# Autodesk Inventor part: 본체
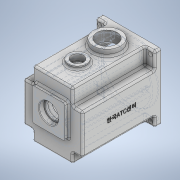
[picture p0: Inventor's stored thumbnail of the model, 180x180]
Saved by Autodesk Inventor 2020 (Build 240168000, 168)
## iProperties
Created: 2022-01
Part Number: 본체
Material: 일반
Document SubType Name: Modeling
Designer: user
Density: 1 g/cm^3
Appearance: 기본값
Mass: 519.685 g
Surface Area: 1174.34 cm^2
Volume: 519.685 cm^3
Author: user
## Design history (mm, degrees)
sketch "스케치1"
  geometry: 1 further point
sketch "스케치2"
  geometry: L1 (-49, 55)-(49, 55); L2 (49, 55)-(49, -55); L3 (49, -55)-(-49, -55); L4 (-49, -55)-(-49, 55); L5 (-49, 55)-(49, -55); L6 (49, 55)-(-49, -55); 1 further point
  constraints: 12 end point, 2 midpoint, 2 parallel, 1 horizontal, 1 perpendicular
  dimensions: "d0" = 98 distance of L2.end L3.end; "d1" = 110 distance of L1.end L2.end
extrude "돌출1" new body sketch "스케치2" distance "d2" = 10; taper "d3" = 0 deg
sketch "스케치3"
  geometry: L1 (49, -55)-(49, 55) reference; L2 (49, 55)-(-49, 55) reference; L3 (-49, 55)-(-49, -55) reference; L4 (-49, -55)-(49, -55) reference; L5 (49, -55)-(49, 55) reference; L6 (49, 55)-(33, 55); L7 (33, 55)-(33, 28); L8 (33, 28)-(49, 28); L9 (49, 28)-(49, 55); L10 (49, -55)-(33, -55); L11 (33, -55)-(33, -38); L12 (33, -38)-(49, -38); L13 (49, -38)-(49, -55); L14 (-49, -55)-(49, -55) reference; L15 (-49, -55)-(-33, -55); L16 (-33, -55)-(-33, -38); L17 (-33, -38)-(-49, -38); L18 (-49, -38)-(-49, -55); L19 (-49, 55)-(-49, -55) reference; L20 (-49, 55)-(-33, 55); L21 (-33, 55)-(-33, 28); L22 (-33, 28)-(-49, 28); L23 (-49, 28)-(-49, 55); 9 further points
  constraints: 32 end point, 8 parallel, 4 horizontal, 4 perpendicular, 1 point on line
  dimensions: "d4" = 27 distance of L6.end L7.end; "d5" = 16 distance of L7.end L8.end; "d6" = 17 distance of L10.end L11.end; "d7" = 16 distance of L11.end L12.end; "d8" = 27 distance of L20.end L21.end; "d9" = 16 distance of L21.end L22.end; "d10" = 16 distance of L16.end L17.end
extrude "돌출2" join sketch "스케치3" distance "d11" = 120; taper "d12" = 0 deg
sketch "스케치4"
  geometry: 1 further point
sketch "스케치5"
  geometry: L1 (49, -55)-(-49, -55) reference; L2 (-26, 48)-(26, 48); L3 (26, 48)-(26, 27.588); L4 (26, 27.588)-(-26, 27.588); L5 (-26, 27.588)-(-26, 48); C1 r 45 at (0, -5); 3 further points
  constraints: 8 end point, 2 parallel, 1 centre point, 1 horizontal, 1 perpendicular, 1 vertical alignment
  dimensions: "d13" = 90 diameter of C1; "d14" = 50 distance from line of L1 C1.centre; "d15" = 53 distance from line of L2 C1.centre; "d16" = 52 distance of L2.start L2.end; "d17" = 26 horizontal distance of C1.centre L2.start
extrude "돌출3" cut sketch "스케치5" distance "d18" = 9; taper "d19" = 0 deg
sketch "스케치6" dims "d27" = 8, "d28" = 8
  geometry: L1 (-26, 31.729)-(-26, 48) reference; L2 (26, 48)-(26, 31.729) reference; L3 (-26, 48)-(26, 48) reference; L4 (-23, 45)-(23, 45); L5 (23, 45)-(23, 21.058); L6 (23, 21.058)-(-23, 21.058); L7 (-23, 21.058)-(-23, 45); L8 (-35.778, -1.006)-(-41.81, -1.006); L9 (-35.778, -8.994)-(-41.81, -8.994); L10 (35.778, -1.006)-(42, -1.006); L11 (35.778, -8.994)-(41.81, -8.994); A1 r 45 centre (0, -5) between (-26, 31.729) and (26, 31.729) reference; A2 r 36 centre (0, -5) between (36, -5) and (-36, -5); A3 r 42 centre (0, -5) between (-41.81, -8.994) and (41.81, -8.994); A4 r 42 centre (0, -5) between (41.81, -1.006) and (-41.81, -1.006); 7 further points
  constraints: 16 end point, 10 point on circle, 4 horizontal, 3 centre point, 2 coincident, 2 horizontal alignment, 2 parallel, 1 perpendicular, 1 point on line, 6 other
  dimensions: "d21" = 46 distance of L4.start L4.end; "d22" = 23 distance from line of A1.centre L7; "d23" = 50 distance from line of A1.centre L4; "d26" = 72 diameter of A2
  node "투영된 루프2"
extrude "돌출4" cut sketch "스케치6" distance "d29" = 112; taper "d30" = 0 deg
fillet "모깎기1" dims "d31" = 3
sketch "스케치8"
  geometry: L1 (98, 0)-(0, 0) reference; C1 r 22.5 at (49, -40); C2 r 15 at (49, -89); 2 further points
  constraints: 2 centre point, 2 vertical alignment, 1 midpoint
  dimensions: "d32" = 45 diameter of C1; "d33" = 30 diameter of C2; "d34" = 40 distance of C1.centre point (49, 0); "d35" = 49 distance of C1.centre C2.centre
extrude "돌출5" join sketch "스케치8" distance "d36" = 10; taper "d37" = 0 deg
sketch "스케치9"
  geometry: C1 r 22.5 at (49, -40) reference; C2 r 15 at (49, -89); 1 further point
  constraints: 1 centre point, 1 vertical alignment
  dimensions: "d38" = 30 diameter of C2; "d39" = 49 distance of C1.centre C2.centre
extrude "돌출6" join sketch "스케치9" distance "d40" = 5; taper "d41" = 0 deg
sketch "스케치10"
  geometry: 1 further point
sketch "스케치11"
  geometry: C1 r 21 at (0, 6); C2 r 15 at (0, -25); C3 r 42 at (0, -5); A1 r 42 centre (0, -5) between (-23, 30.143) and (-41.319, 2.532) reference; 3 further points
  constraints: 3 centre point, 2 vertical alignment, 1 coincident
  dimensions: "d42" = 42 diameter of C1; "d43" = 30 diameter of C2; "d44" = 20 distance of C2.centre C3.centre; "d45" = 11 distance of C1.centre C3.centre
sketch "스케치12"
  geometry: C1 r 22.5 at (0, 0) reference; 2 further points
  constraints: 1 coincident
hole "구멍1" sketch "스케치12" at (0, 0) diameter "d46" = 33.376; stored, may be unused: countersink angle "d50" = 90 deg, drill point angle "d52" = 118 deg; dims "d47" = 70, "d48" = 4, "d49" = 2, "d51" = 77.3
extrude "돌출7" join sketch "스케치11" distance "d53" = 7; taper "d54" = 0 deg
sketch "스케치13"
  geometry: C1 r 11 at (0, -25); A1 r 15 centre (0, -25) between (-8.978, -12.984) and (8.978, -12.984) reference; 1 further point
  constraints: 1 centre point, 1 coincident
  dimensions: "d55" = 22 diameter of C1
extrude "돌출8" cut sketch "스케치13" distance "d56" = 7; taper "d57" = 0 deg
sketch "스케치14"
  geometry: C1 r 17.5 at (0, 6); A1 r 21 centre (0, 6) between (8.978, -12.984) and (-8.978, -12.984) reference; 1 further point
  constraints: 1 centre point, 1 coincident
  dimensions: "d58" = 35 diameter of C1
extrude "돌출9" cut sketch "스케치14" distance "d59" = 10; taper "d60" = 0 deg
sketch "스케치15"
  geometry: C1 r 11 at (0, 0) reference; C2 r 9.5 at (0, 0); 1 further point
  constraints: 1 centre point, 1 coincident
  dimensions: "d61" = 19 diameter of C2
extrude "돌출10" cut sketch "스케치15" distance "d62" = 3; taper "d63" = 0 deg
sketch "스케치16"
  geometry: C1 r 17.5 at (0, 0) reference; C2 r 14 at (0, 0); 1 further point
  constraints: 1 centre point, 1 coincident
  dimensions: "d64" = 28 diameter of C2
sketch "스케치17"
  geometry: 1 further point
sketch "스케치18"
  geometry: 1 further point
sketch "스케치19"
  geometry: L1 (-27, 33)-(27, 33); L2 (27, 33)-(27, -21); L3 (27, -21)-(-27, -21); L4 (-27, -21)-(-27, 33); L5 (-27, 33)-(27, -21); L6 (27, 33)-(-27, -21); 4 further points
  constraints: 12 end point, 3 midpoint, 2 parallel, 1 coincident, 1 horizontal, 1 perpendicular
  dimensions: "d65" = 54 distance of L2.end L3.end; "d66" = 54 distance of L1.end L2.end
extrude "돌출11" join sketch "스케치19" distance "d67" = 7; taper "d68" = 0 deg
sketch "스케치20"
  geometry: C1 r 16 at (0, 6); A1 r 21 centre (0, 6) between (8.978, -12.984) and (-8.978, -12.984) reference; 1 further point
  constraints: 1 centre point, 1 coincident
  dimensions: "d69" = 32 diameter of C1
extrude "돌출12" cut sketch "스케치20" distance "d70" = 8.3; taper "d71" = 0 deg
sketch "스케치21"
  geometry: C1 r 16 at (0, 0) reference; C2 r 14 at (0, 0); 1 further point
  constraints: 1 centre point, 1 coincident
  dimensions: "d72" = 28 diameter of C2
extrude "돌출13" cut sketch "스케치21" distance "d73" = 8.3; taper "d74" = 0 deg
sketch "스케치22"
  geometry: 1 further point
sketch "스케치23"
  geometry: C1 r 15 at (23, 80) reference; C2 r 15 at (23, 80); 1 further point
  constraints: 1 centre point, 1 coincident
  dimensions: "d75" = 30 diameter of C2
extrude "돌출14" cut sketch "스케치23" distance "d76" = 5; taper "d77" = 0 deg
sketch "스케치24"
  geometry: C1 r 15 at (0, 0) reference; C2 r 10 at (0, 0); 1 further point
  constraints: 1 centre point, 1 coincident
  dimensions: "d78" = 20 diameter of C2
extrude "돌출15" cut sketch "스케치24" stored distance "d79" = 5; taper "d80" = 0 deg
sketch "스케치25"
  geometry: L1 (33, -55)-(49, -55) reference; L2 (49, -55)-(49, -38) reference; L3 (-49, -38)-(-49, -55) reference; L4 (-49, -55)-(-33, -55) reference; L5 (-33, 55)-(-49, 55) reference; L6 (-49, 55)-(-49, 28) reference; L7 (49, 55)-(33, 55) reference; L8 (49, 28)-(49, 55) reference; C1 r 3.5 at (42, -48); C2 r 3.5 at (-42, -48); C3 r 3.5 at (-42, 48); C4 r 3.5 at (42, 48); 1 further point
  constraints: 4 centre point
  dimensions: "d81" = 7 diameter of C1; "d82" = 7 diameter of C2; "d83" = 7 diameter of C3; "d84" = 7 diameter of C4; "d85" = 7 distance from line of L1 C1.centre; "d86" = 7 distance from line of L2 C1.centre; "d87" = 7 distance from line of L3 C2.centre; "d88" = 7 distance from line of L4 C2.centre; "d89" = 7 distance from line of L5 C3.centre; "d90" = 7 distance from line of L6 C3.centre; "d91" = 7 distance from line of L7 C4.centre; "d92" = 7 distance from line of L8 C4.centre
extrude "돌출16" cut sketch "스케치25" distance "d93" = 10; taper "d94" = 0 deg
sketch "스케치26"
  geometry: A1 r 4 centre (-36, -5) between (-36.222, -8.994) and (-36.222, -1.006) reference; A2 r 4 centre (36, -5) between (36.222, -1.006) and (36.222, -8.994) reference; 3 further points
  constraints: 2 coincident
hole "구멍2" sketch "스케치26" at (-36, -5), (36, -5) diameter "d95" = 3.242; stored, may be unused: countersink angle "d99" = 90 deg, drill point angle "d101" = 118 deg; dims "d96" = 7, "d97" = 4, "d98" = 2, "d100" = 9
fillet "모깎기2" dims "d102" = 6
fillet "모깎기3" dims "d103" = 6
fillet "모깎기4" dims "d104" = 3
chamfer "모따기1" distance "d105" = 1; stored, may be unused: second distance "d106" = 2, angle "d107" = 45 deg
fillet "모깎기5" dims "d108" = 3
fillet "모깎기6" dims "d109" = 0.3
chamfer "모따기2" distance "d110" = 1; stored, may be unused: second distance "d111" = 2, angle "d112" = 45 deg
fillet "모깎기7" dims "d113" = 0.3
chamfer "모따기3" distance "d114" = 1; stored, may be unused: second distance "d115" = 2, angle "d116" = 45 deg
fillet "모깎기8" dims "d117" = 3
fillet "모깎기9" dims "d118" = 3
fillet "모깎기10" dims "d119" = 3
fillet "모깎기11" dims "d120" = 3
fillet "모깎기12" dims "d121" = 3
fillet "모깎기13" dims "d122" = 3
sketch "스케치27"
  geometry: 1 further point
fillet "모깎기14" dims "d123" = 3
sketch "스케치28"
  geometry: 1 further point
sketch "스케치29"
  geometry: L1 (-3, 60)-(-3, 0) reference; L2 (114, 90)-(0, 90) reference; 2 further points
  constraints: 1 other
  dimensions: "d124" = 65 distance from line of L1 point (62, 30); "d125" = 60 distance from line of L2 point (62, 30)
feature "엠보싱1" sketch "스케치29" dims "d4" = 27, "d5" = 16, "d126" = 0.5, "d127" = 0
fillet "모깎기15" dims "d128" = 3
fillet "모깎기16" dims "d129" = 3
fillet "모깎기17" dims "d130" = 3
node "솔리드1"
node "투영된 루프1"
node "투영된 루프3"
feature "A9D066F2-1C7D-4E18-AEED-F7BC21143FA4" dims "d46" = 33.376, "d47" = 70, "d48" = 4, "d49" = 2, "d50" = 90 deg, "d51" = 77.3, "d52" = 118 deg
other parameters: "d20" = 84
